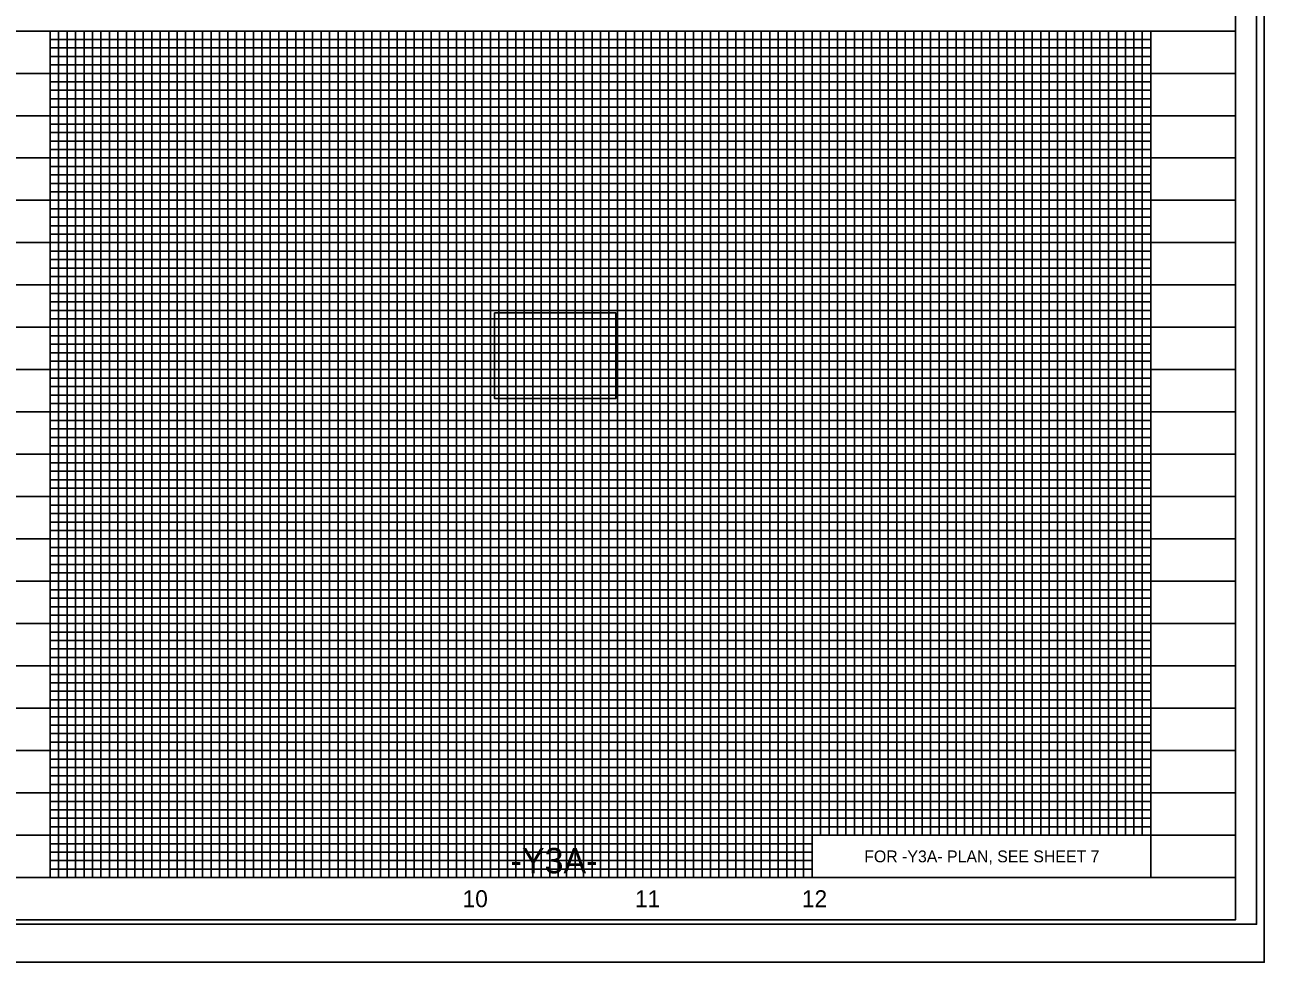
# Model space of a CAD drawing. Extents: x 1629787 to 1631995, y 1166253 to 1167353.
# Drawn here: x 1630739 to 1631471, y 1166253 to 1166807 of the extents above; entities that cross this region are included whole.
import ezdxf

# ---------------------------------------------------------------- set-up
doc = ezdxf.new("R2010")
doc.units = 0
for name, color, linetype in [('Exist Vertical Profile Horizontal Axis Label Major', 7, 'Continuous'), ('Prop Grid Mask', 7, 'Continuous'), ('Sheet Data Field CELL', 7, 'Continuous'), ('Sheet Layout Profile Border Port 1', 7, 'Continuous'), ('Sheet Plot Border Inside CELL', 7, 'Continuous'), ('Sheet Plot Border Outside CELL', 7, 'Continuous'), ('Sheet Profile CELL', 7, 'Continuous'), ('Sheet Profile Grid Major CELL', 7, 'Continuous'), ('Sheet Profile Grid Middle CELL', 7, 'Continuous'), ('Sheet Profile Grid Minor CELL', 7, 'Continuous')]:
    doc.layers.add(name, color=color, linetype=linetype)

msp = doc.modelspace()

# ---------------------------------------------------------------- linework, layer by layer
at = {"layer": 'Prop Grid Mask'}
for points in [[(1631016.75, 1166636.96), (1631088.35, 1166636.96), (1631088.35, 1166586.26), (1631016.75, 1166586.26)], [(1631204.31, 1166328.4), (1631404.31, 1166328.4), (1631404.31, 1166303.4), (1631204.31, 1166303.4)], [(1630974.31, 1166323.4), (1631134.31, 1166323.4), (1631134.31, 1166303.4), (1630974.31, 1166303.4)]]:
    msp.add_lwpolyline(points, close=True, dxfattribs=at)
at = {"layer": 'Sheet Data Field CELL'}
msp.add_lwpolyline([(1631404.31, 1166303.4), (1631204.31, 1166303.4), (1631204.31, 1166328.4), (1631404.31, 1166328.4)], close=True, dxfattribs=at)
at = {"layer": 'Sheet Layout Profile Border Port 1'}
msp.add_lwpolyline([(1630754.31, 1166803.4), (1631404.31, 1166803.4), (1631404.31, 1166303.4), (1630754.31, 1166303.4)], close=True, dxfattribs=at)
at = {"layer": 'Sheet Plot Border Inside CELL'}
msp.add_lwpolyline([(1629800.31, 1166275.85), (1631466.81, 1166275.85), (1631466.81, 1167330.95), (1629800.31, 1167330.95)], close=True, dxfattribs=at)
at = {"layer": 'Sheet Plot Border Outside CELL'}
msp.add_lwpolyline([(1629787.31, 1166253.4), (1631471.31, 1166253.4), (1631471.31, 1167353.4), (1629787.31, 1167353.4)], close=True, dxfattribs=at)
at = {"layer": 'Sheet Profile CELL'}
for p, q in [((1629954.31, 1166803.4), (1631454.31, 1166803.4)), ((1631454.31, 1166303.4), (1629954.31, 1166303.4)), ((1629954.31, 1166278.4), (1631454.31, 1166278.4))]:
    msp.add_line(p, q, dxfattribs=at)
msp.add_lwpolyline([(1631454.31, 1167328.4), (1629954.31, 1167328.4), (1629954.31, 1166278.4), (1631454.31, 1166278.4)], close=True, dxfattribs=at)
at = {"layer": 'Sheet Profile Grid Major CELL'}
for p, q in [((1630754.31, 1166803.4), (1630804.31, 1166803.4)), ((1630754.31, 1166303.4), (1630754.31, 1166803.4)), ((1630754.31, 1166803.4), (1630804.31, 1166803.4)), ((1630804.31, 1166803.4), (1630804.31, 1166303.4)), ((1630854.31, 1166803.4), (1630904.31, 1166803.4)), ((1630854.31, 1166303.4), (1630854.31, 1166803.4)), ((1630854.31, 1166803.4), (1630904.31, 1166803.4)), ((1630904.31, 1166803.4), (1630904.31, 1166303.4)), ((1630954.31, 1166803.4), (1631004.31, 1166803.4)), ((1630954.31, 1166303.4), (1630954.31, 1166803.4)), ((1630954.31, 1166803.4), (1631004.31, 1166803.4)), ((1631004.31, 1166803.4), (1631004.31, 1166303.4)), ((1631054.31, 1166803.4), (1631104.31, 1166803.4)), ((1631054.31, 1166303.4), (1631054.31, 1166803.4)), ((1631054.31, 1166803.4), (1631104.31, 1166803.4)), ((1631104.31, 1166803.4), (1631104.31, 1166303.4)), ((1631154.31, 1166803.4), (1631204.31, 1166803.4)), ((1631154.31, 1166303.4), (1631154.31, 1166803.4)), ((1631154.31, 1166803.4), (1631204.31, 1166803.4)), ((1631204.31, 1166803.4), (1631204.31, 1166303.4)), ((1631254.31, 1166803.4), (1631304.31, 1166803.4)), ((1631354.31, 1166803.4), (1631404.31, 1166803.4)), ((1631354.31, 1166803.4), (1631404.31, 1166803.4)), ((1631354.31, 1166328.4), (1631354.31, 1166803.4)), ((1631404.31, 1166803.4), (1631404.31, 1166303.4)), ((1630804.31, 1166303.4), (1630854.31, 1166303.4)), ((1630904.31, 1166303.4), (1630954.31, 1166303.4)), ((1631004.31, 1166303.4), (1631054.31, 1166303.4)), ((1631104.31, 1166303.4), (1631154.31, 1166303.4))]:
    msp.add_line(p, q, dxfattribs=at)
for points in [[(1631254.31, 1166328.4), (1631254.31, 1166803.4), (1631304.31, 1166803.4), (1631304.31, 1166328.4)], [(1631454.31, 1166778.4), (1629954.31, 1166778.4)], [(1631454.31, 1166728.4), (1629954.31, 1166728.4)], [(1631454.31, 1166678.4), (1629954.31, 1166678.4), (1629954.31, 1166628.4), (1631454.31, 1166628.4)], [(1631454.31, 1166578.4), (1629954.31, 1166578.4), (1629954.31, 1166528.4), (1631454.31, 1166528.4)], [(1631454.31, 1166478.4), (1629954.31, 1166478.4), (1629954.31, 1166428.4), (1631454.31, 1166428.4)], [(1631454.31, 1166378.4), (1629954.31, 1166378.4), (1629954.31, 1166378.4), (1629954.31, 1166328.4), (1631454.31, 1166328.4)], [(1631454.31, 1166303.4), (1629954.31, 1166303.4)]]:
    msp.add_lwpolyline(points, dxfattribs=at)
at = {"layer": 'Sheet Profile Grid Middle CELL'}
for points in [[(1630779.31, 1166303.4), (1630779.31, 1166803.4), (1630829.31, 1166803.4), (1630829.31, 1166303.4), (1630879.31, 1166303.4), (1630879.31, 1166803.4), (1630929.31, 1166803.4), (1630929.31, 1166303.4), (1630979.31, 1166303.4), (1630979.31, 1166803.4), (1631029.31, 1166803.4), (1631029.31, 1166303.4), (1631079.31, 1166303.4), (1631079.31, 1166803.4), (1631129.31, 1166803.4), (1631129.31, 1166303.4), (1631179.31, 1166303.4)], [(1631179.31, 1166303.4), (1631179.31, 1166803.4), (1631229.31, 1166803.4), (1631229.31, 1166328.4)], [(1631279.31, 1166328.4), (1631279.31, 1166803.4), (1631329.31, 1166803.4), (1631329.31, 1166328.4)], [(1631379.31, 1166328.4), (1631379.31, 1166803.4)], [(1629954.31, 1166753.4), (1631454.31, 1166753.4)], [(1631454.31, 1166703.4), (1629954.31, 1166703.4), (1629954.31, 1166653.4), (1631454.31, 1166653.4)], [(1631454.31, 1166603.4), (1629954.31, 1166603.4), (1629954.31, 1166553.4), (1631454.31, 1166553.4)], [(1631454.31, 1166503.4), (1629954.31, 1166503.4), (1629954.31, 1166453.4), (1631454.31, 1166453.4)], [(1631454.31, 1166403.4), (1629954.31, 1166403.4), (1629954.31, 1166353.4), (1631454.31, 1166353.4)], [(1631454.31, 1166303.4), (1629954.31, 1166303.4)]]:
    msp.add_lwpolyline(points, dxfattribs=at)
at = {"layer": 'Sheet Profile Grid Minor CELL'}
for p, q in [((1630749.31, 1166803.4), (1630759.31, 1166803.4)), ((1630759.31, 1166803.4), (1630759.31, 1166303.4)), ((1630764.31, 1166303.4), (1630764.31, 1166803.4)), ((1630764.31, 1166803.4), (1630769.31, 1166803.4)), ((1630769.31, 1166803.4), (1630769.31, 1166303.4)), ((1630774.31, 1166303.4), (1630774.31, 1166803.4)), ((1630774.31, 1166803.4), (1630784.31, 1166803.4)), ((1630784.31, 1166803.4), (1630784.31, 1166303.4)), ((1630789.31, 1166303.4), (1630789.31, 1166803.4)), ((1630789.31, 1166803.4), (1630794.31, 1166803.4)), ((1630794.31, 1166803.4), (1630794.31, 1166303.4)), ((1630799.31, 1166303.4), (1630799.31, 1166803.4)), ((1630799.31, 1166803.4), (1630809.31, 1166803.4)), ((1630809.31, 1166803.4), (1630809.31, 1166303.4)), ((1630814.31, 1166303.4), (1630814.31, 1166803.4)), ((1630814.31, 1166803.4), (1630819.31, 1166803.4)), ((1630819.31, 1166803.4), (1630819.31, 1166303.4)), ((1630824.31, 1166303.4), (1630824.31, 1166803.4)), ((1630824.31, 1166803.4), (1630834.31, 1166803.4)), ((1630834.31, 1166803.4), (1630834.31, 1166303.4)), ((1630754.31, 1166798.4), (1631404.31, 1166798.4)), ((1631404.31, 1166793.4), (1630754.31, 1166793.4)), ((1630754.31, 1166788.4), (1631404.31, 1166788.4)), ((1631404.31, 1166783.4), (1630754.31, 1166783.4)), ((1630754.31, 1166773.4), (1631404.31, 1166773.4)), ((1631404.31, 1166768.4), (1630754.31, 1166768.4)), ((1630754.31, 1166763.4), (1631404.31, 1166763.4)), ((1631404.31, 1166758.4), (1630754.31, 1166758.4)), ((1630754.31, 1166748.4), (1631404.31, 1166748.4)), ((1631404.31, 1166743.4), (1630754.31, 1166743.4)), ((1630754.31, 1166738.4), (1631404.31, 1166738.4)), ((1631404.31, 1166733.4), (1630754.31, 1166733.4)), ((1630754.31, 1166723.4), (1631404.31, 1166723.4)), ((1631404.31, 1166718.4), (1630754.31, 1166718.4)), ((1630754.31, 1166713.4), (1631404.31, 1166713.4)), ((1631404.31, 1166708.4), (1630754.31, 1166708.4)), ((1630754.31, 1166698.4), (1631404.31, 1166698.4)), ((1631404.31, 1166693.4), (1630754.31, 1166693.4)), ((1630754.31, 1166688.4), (1631404.31, 1166688.4)), ((1631404.31, 1166683.4), (1630754.31, 1166683.4)), ((1630754.31, 1166673.4), (1631404.31, 1166673.4)), ((1631404.31, 1166668.4), (1630754.31, 1166668.4)), ((1630754.31, 1166663.4), (1631404.31, 1166663.4)), ((1631404.31, 1166658.4), (1630754.31, 1166658.4)), ((1630754.31, 1166648.4), (1631404.31, 1166648.4)), ((1631404.31, 1166643.4), (1630754.31, 1166643.4)), ((1630754.31, 1166638.4), (1631404.31, 1166638.4)), ((1631404.31, 1166633.4), (1630754.31, 1166633.4)), ((1630754.31, 1166623.4), (1631404.31, 1166623.4)), ((1631404.31, 1166618.4), (1630754.31, 1166618.4)), ((1630754.31, 1166613.4), (1631404.31, 1166613.4)), ((1631404.31, 1166608.4), (1630754.31, 1166608.47)), ((1630754.31, 1166598.4), (1631404.31, 1166598.4)), ((1631404.31, 1166593.4), (1630754.31, 1166593.4)), ((1630754.31, 1166588.4), (1631404.31, 1166588.4)), ((1631404.31, 1166583.4), (1630754.31, 1166583.4)), ((1630754.31, 1166573.4), (1631404.31, 1166573.4)), ((1631404.31, 1166568.4), (1630754.31, 1166568.4)), ((1630754.31, 1166563.4), (1631404.31, 1166563.4)), ((1631404.31, 1166558.4), (1630754.31, 1166558.4)), ((1630754.31, 1166548.4), (1631404.31, 1166548.4)), ((1631404.31, 1166543.4), (1630754.31, 1166543.4)), ((1630754.31, 1166538.4), (1631404.31, 1166538.4)), ((1631404.31, 1166533.4), (1630754.31, 1166533.4)), ((1630754.31, 1166523.4), (1631404.31, 1166523.4)), ((1631404.31, 1166518.4), (1630754.31, 1166518.4)), ((1630754.31, 1166513.4), (1631404.31, 1166513.4)), ((1631404.31, 1166508.4), (1630754.31, 1166508.4)), ((1630754.31, 1166498.4), (1631404.31, 1166498.4)), ((1631404.31, 1166493.4), (1630754.31, 1166493.4)), ((1630754.31, 1166488.4), (1631404.31, 1166488.4)), ((1631404.31, 1166483.4), (1630754.31, 1166483.4)), ((1630754.31, 1166473.4), (1631404.31, 1166473.4)), ((1631404.31, 1166468.4), (1630754.31, 1166468.4)), ((1630754.31, 1166463.4), (1631404.31, 1166463.4)), ((1631404.31, 1166458.4), (1630754.31, 1166458.4)), ((1630754.31, 1166448.4), (1631404.31, 1166448.4)), ((1631404.31, 1166443.4), (1630754.31, 1166443.4)), ((1630754.31, 1166438.4), (1631404.31, 1166438.4)), ((1631404.31, 1166433.4), (1630754.31, 1166433.4)), ((1630754.31, 1166423.4), (1631404.31, 1166423.4)), ((1631404.31, 1166418.4), (1630754.31, 1166418.4)), ((1630754.31, 1166413.4), (1631404.31, 1166413.4)), ((1631404.31, 1166408.4), (1630754.31, 1166408.4)), ((1630754.31, 1166398.4), (1631404.31, 1166398.4)), ((1631404.31, 1166393.4), (1630754.31, 1166393.4)), ((1630754.31, 1166388.4), (1631404.31, 1166388.4)), ((1631404.31, 1166383.4), (1630754.31, 1166383.4)), ((1630754.31, 1166373.4), (1631404.31, 1166373.4)), ((1631404.31, 1166368.4), (1630754.31, 1166368.4)), ((1630754.31, 1166363.4), (1631404.31, 1166363.4)), ((1631404.31, 1166358.4), (1630754.31, 1166358.4)), ((1630754.31, 1166348.4), (1631404.31, 1166348.4)), ((1631404.31, 1166343.4), (1630754.31, 1166343.4)), ((1630754.31, 1166338.4), (1631404.31, 1166338.4)), ((1631404.31, 1166333.4), (1630754.31, 1166333.4)), ((1630754.31, 1166323.4), (1631204.31, 1166323.4)), ((1631204.31, 1166318.4), (1630754.31, 1166318.4)), ((1630754.31, 1166313.4), (1631204.31, 1166313.4)), ((1630754.31, 1166308.4), (1631204.31, 1166308.4)), ((1630784.31, 1166303.4), (1630789.31, 1166303.4)), ((1630794.31, 1166303.4), (1630799.31, 1166303.4)), ((1630809.31, 1166303.4), (1630814.31, 1166303.4)), ((1630819.31, 1166303.4), (1630824.31, 1166303.4)), ((1630834.31, 1166303.4), (1630839.31, 1166303.4))]:
    msp.add_line(p, q, dxfattribs=at)
for points in [[(1630839.31, 1166303.4), (1630839.31, 1166803.4), (1630844.31, 1166803.4), (1630844.31, 1166303.4), (1630849.31, 1166303.4), (1630849.31, 1166803.4), (1630859.31, 1166803.4), (1630859.31, 1166303.4), (1630864.31, 1166303.4), (1630864.31, 1166803.4), (1630869.31, 1166803.4), (1630869.31, 1166303.4), (1630874.31, 1166303.4), (1630874.31, 1166803.4), (1630884.31, 1166803.4), (1630884.31, 1166303.4), (1630889.31, 1166303.4), (1630889.31, 1166803.4), (1630894.31, 1166803.4), (1630894.31, 1166303.4), (1630899.31, 1166303.4), (1630899.31, 1166803.4), (1630909.31, 1166803.4), (1630909.31, 1166303.4), (1630914.31, 1166303.4), (1630914.31, 1166803.4), (1630919.31, 1166803.4), (1630919.31, 1166303.4), (1630924.31, 1166303.4), (1630924.31, 1166803.4), (1630934.31, 1166803.4), (1630934.31, 1166303.4), (1630939.31, 1166303.4), (1630939.31, 1166803.4), (1630944.31, 1166803.4), (1630944.31, 1166303.4), (1630949.31, 1166303.4), (1630949.31, 1166803.4), (1630959.31, 1166803.4), (1630959.31, 1166303.4), (1630964.31, 1166303.4), (1630964.31, 1166803.4), (1630969.31, 1166803.4), (1630969.31, 1166303.4), (1630974.31, 1166303.4), (1630974.31, 1166803.4), (1630984.31, 1166803.4), (1630984.31, 1166303.4), (1630989.31, 1166303.4), (1630989.31, 1166803.4), (1630994.31, 1166803.4), (1630994.31, 1166303.4), (1630999.31, 1166303.4), (1630999.31, 1166803.4), (1631009.31, 1166803.4), (1631009.31, 1166303.4), (1631014.31, 1166303.4), (1631014.31, 1166803.4), (1631019.31, 1166803.4), (1631019.31, 1166303.4), (1631024.31, 1166303.4), (1631024.31, 1166803.4), (1631034.31, 1166803.4), (1631034.31, 1166303.4), (1631039.31, 1166303.4), (1631039.31, 1166803.4), (1631044.31, 1166803.4), (1631044.31, 1166303.4), (1631049.31, 1166303.4), (1631049.31, 1166803.4), (1631059.31, 1166803.4), (1631059.31, 1166303.4), (1631064.31, 1166303.4), (1631064.31, 1166803.4), (1631069.31, 1166803.4), (1631069.31, 1166303.4), (1631074.31, 1166303.4), (1631074.31, 1166803.4), (1631084.31, 1166803.4), (1631084.31, 1166303.4), (1631089.31, 1166303.4), (1631089.31, 1166803.4), (1631094.31, 1166803.4), (1631094.31, 1166303.4), (1631099.31, 1166303.4), (1631099.31, 1166803.4), (1631109.31, 1166803.4), (1631109.31, 1166303.4), (1631114.31, 1166303.4), (1631114.31, 1166803.4), (1631119.31, 1166803.4), (1631119.31, 1166303.4), (1631124.31, 1166303.4), (1631124.31, 1166803.4), (1631134.31, 1166803.4), (1631134.31, 1166303.4), (1631139.31, 1166303.4), (1631139.31, 1166803.4), (1631144.31, 1166803.4), (1631144.31, 1166303.4)], [(1631144.31, 1166303.4), (1631149.31, 1166303.4), (1631149.31, 1166803.4), (1631159.31, 1166803.4), (1631159.31, 1166303.4)], [(1631164.31, 1166303.4), (1631164.31, 1166803.4), (1631169.31, 1166803.4), (1631169.31, 1166303.4)], [(1631174.31, 1166303.4), (1631174.31, 1166803.4), (1631184.31, 1166803.4), (1631184.31, 1166303.4)], [(1631189.31, 1166303.4), (1631189.31, 1166803.4), (1631194.31, 1166803.4), (1631194.31, 1166303.4)], [(1631199.31, 1166303.4), (1631199.31, 1166803.4), (1631209.31, 1166803.4), (1631209.31, 1166328.4)], [(1631214.31, 1166328.4), (1631214.31, 1166803.4), (1631219.31, 1166803.4), (1631219.31, 1166328.4)], [(1631224.31, 1166328.4), (1631224.31, 1166803.4), (1631234.31, 1166803.4), (1631234.31, 1166328.4)], [(1631239.31, 1166328.4), (1631239.31, 1166803.4), (1631244.31, 1166803.4), (1631244.31, 1166328.4)], [(1631249.31, 1166328.4), (1631249.31, 1166803.4), (1631259.31, 1166803.4), (1631259.31, 1166328.4)], [(1631264.31, 1166328.4), (1631264.31, 1166803.4), (1631269.31, 1166803.4), (1631269.31, 1166328.4)], [(1631274.31, 1166328.4), (1631274.31, 1166803.4), (1631284.31, 1166803.4), (1631284.31, 1166328.4)], [(1631289.31, 1166328.4), (1631289.31, 1166803.4), (1631294.31, 1166803.4), (1631294.31, 1166328.4)], [(1631299.31, 1166328.4), (1631299.31, 1166803.4), (1631309.31, 1166803.4), (1631309.31, 1166328.4)], [(1631314.31, 1166328.4), (1631314.31, 1166803.4), (1631319.31, 1166803.4), (1631319.31, 1166328.4)], [(1631324.31, 1166328.4), (1631324.31, 1166803.4), (1631334.31, 1166803.4), (1631334.31, 1166328.4)], [(1631339.31, 1166328.4), (1631339.31, 1166803.4), (1631344.31, 1166803.4), (1631344.31, 1166328.4)], [(1631349.31, 1166328.4), (1631349.31, 1166803.4), (1631359.31, 1166803.4), (1631359.31, 1166328.4)], [(1631364.31, 1166328.4), (1631364.31, 1166803.4), (1631369.31, 1166803.4), (1631369.31, 1166328.4)], [(1631374.31, 1166328.4), (1631374.31, 1166803.4), (1631384.31, 1166803.4), (1631384.31, 1166328.4)], [(1631389.31, 1166328.4), (1631389.31, 1166803.4), (1631394.31, 1166803.4), (1631394.31, 1166328.4)], [(1631399.31, 1166328.4), (1631399.31, 1166803.4), (1631404.31, 1166803.4)]]:
    msp.add_lwpolyline(points, dxfattribs=at)

# ---------------------------------------------------------------- texts
at = {"layer": 'Exist Vertical Profile Horizontal Axis Label Major'}
for s, p in [('10', (1630997.9, 1166285.9)), ('11', (1631099.74, 1166285.9)), ('12', (1631198.3, 1166285.9))]:
    msp.add_text(s, height=10, dxfattribs=at).set_placement(p)
at = {"layer": 'Sheet Data Field CELL'}
for s, height, p in [('-Y3A-', 15, (1631026.25, 1166305.9)), ('FOR -Y3A- PLAN, SEE SHEET 7', 7, (1631235.1, 1166312.4))]:
    msp.add_text(s, height=height, rotation=360, dxfattribs=at).set_placement(p)

doc.saveas('drawing.dxf')
